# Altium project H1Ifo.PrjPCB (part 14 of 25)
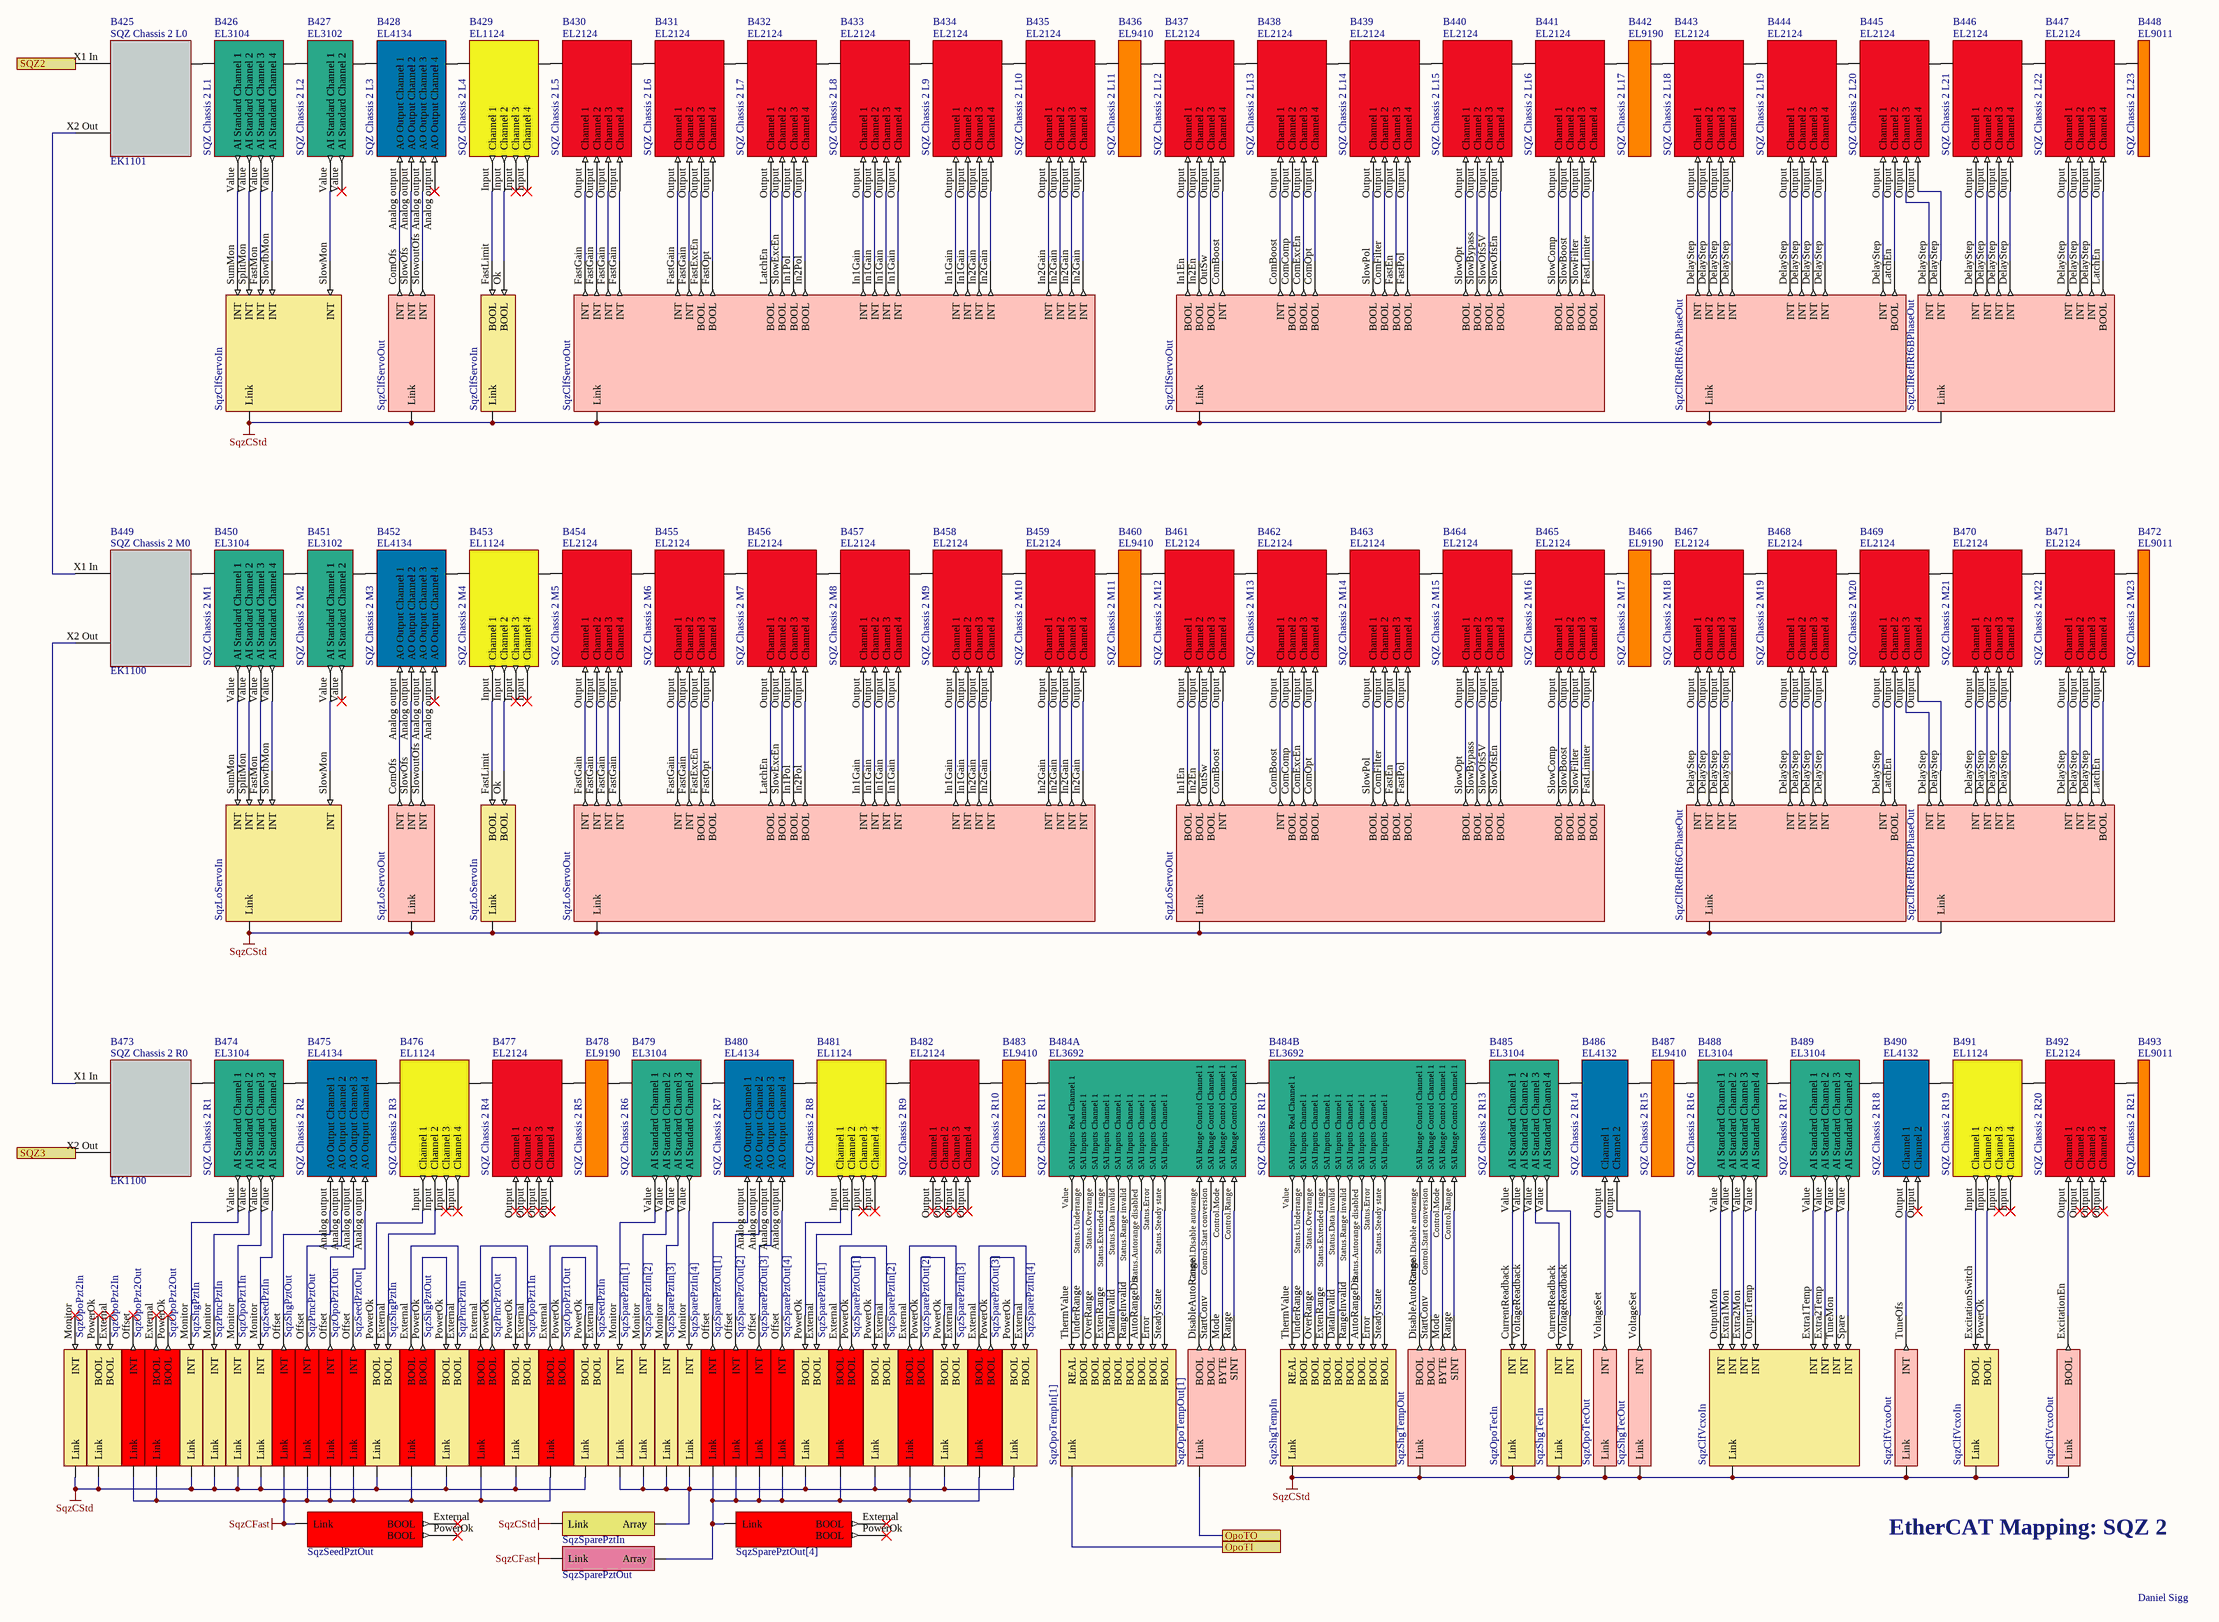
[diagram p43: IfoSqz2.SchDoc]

## Sheet IfoSqz2.SchDoc: D1800185 (continued)

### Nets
SqzCFast: V309.0(Link) V309.1(Link) V310.0(Link) V310.1(Link) V311.0(Link) V311.1(Link) V312.0(Link) V312.1(Link) V458.?1(Link) V668.0(Link) V668.1(Link)
SqzCStd: V176.1(Link) V177.1(Link) V289.0(Link) V289.1(Link) V290.0(Link) V290.1(Link) V290.2(Link) V291.0(Link) V291.1(Link) V292.0(Link) V292.1(Link) V292.2(Link) V297.1(Link) V298.1(Link) V303.0(Link) V303.1(Link) V304.0(Link) V304.1(Link) V305.0(Link) V305.1(Link) V306.0(Link) V306.1(Link) V307.0(Link) V307.1(Link) V308.0(Link) V308.1(Link) V448.?1(Link) V449.?1(Link) V450.?1(Link) V452.?1(Link) V455.1(Link) V456.1(Link) V457.?1(Link) V655.0(Link) V655.1(Link)
NetB409_X2 Out: B425.X1_In(A) ; port SQZ2
NetB425_Ebus: B425.Ebus(B) B426.Ebus(A)
NetB425_X2 Out: B425.X2_Out(C) B449.X1_In(A)
NetB426_Ebus: B426.Ebus(B) B427.Ebus(A)
NetB426_Value: B426.Value(AI_Standard_Channel_1) V291.SumMon(INT)
NetB426_Value: B426.Value(AI_Standard_Channel_2) V291.SplitMon(INT)  [a separate net that carries the same name]
NetB426_Value: B426.Value(AI_Standard_Channel_3) V291.FastMon(INT)  [a separate net that carries the same name]
NetB426_Value: B426.Value(AI_Standard_Channel_4) V291.SlowfbMon(INT)  [a separate net that carries the same name]
NetB427_Ebus: B427.Ebus(B) B428.Ebus(A)
NetB427_Value: B427.Value(AI_Standard_Channel_1) V291.SlowMon(INT)
NetB428_Analog output: B428.Analog_output(AO_Output_Channel_1) V292.ComOfs(INT)
NetB428_Analog output: B428.Analog_output(AO_Output_Channel_2) V292.SlowOfs(INT)  [a separate net that carries the same name]
NetB428_Analog output: B428.Analog_output(AO_Output_Channel_3) V292.SlowoutOfs(INT)  [a separate net that carries the same name]
NetB428_Ebus: B428.Ebus(B) B429.Ebus(A)
NetB429_Ebus: B429.Ebus(B) B430.Ebus(A)
NetB429_Input: B429.Input(Channel_1) V291.FastLimit(BOOL)
NetB429_Input: B429.Input(Channel_2) V291.Ok(BOOL)  [a separate net that carries the same name]
NetB430_Ebus: B430.Ebus(B) B431.Ebus(A)
NetB430_Output: B430.Output(Channel_1) V292.FastGain(INT)
NetB430_Output: B430.Output(Channel_2) V292.FastGain(INT)  [a separate net that carries the same name]
NetB430_Output: B430.Output(Channel_3) V292.FastGain(INT)  [a separate net that carries the same name]
NetB430_Output: B430.Output(Channel_4) V292.FastGain(INT)  [a separate net that carries the same name]
NetB431_Ebus: B431.Ebus(B) B432.Ebus(A)
NetB431_Output: B431.Output(Channel_1) V292.FastGain(INT)
NetB431_Output: B431.Output(Channel_2) V292.FastGain(INT)  [a separate net that carries the same name]
NetB431_Output: B431.Output(Channel_3) V292.FastExcEn(BOOL)  [a separate net that carries the same name]
NetB431_Output: B431.Output(Channel_4) V292.FastOpt(BOOL)  [a separate net that carries the same name]
NetB432_Ebus: B432.Ebus(B) B433.Ebus(A)
NetB432_Output: B432.Output(Channel_1) V292.LatchEn(BOOL)
NetB432_Output: B432.Output(Channel_2) V292.SlowExcEn(BOOL)  [a separate net that carries the same name]
NetB432_Output: B432.Output(Channel_3) V292.In1Pol(BOOL)  [a separate net that carries the same name]
NetB432_Output: B432.Output(Channel_4) V292.In2Pol(BOOL)  [a separate net that carries the same name]
NetB433_Ebus: B433.Ebus(B) B434.Ebus(A)
NetB433_Output: B433.Output(Channel_1) V292.In1Gain(INT)
NetB433_Output: B433.Output(Channel_2) V292.In1Gain(INT)  [a separate net that carries the same name]
NetB433_Output: B433.Output(Channel_3) V292.In1Gain(INT)  [a separate net that carries the same name]
NetB433_Output: B433.Output(Channel_4) V292.In1Gain(INT)  [a separate net that carries the same name]
NetB434_Ebus: B434.Ebus(B) B435.Ebus(A)
NetB434_Output: B434.Output(Channel_1) V292.In1Gain(INT)
NetB434_Output: B434.Output(Channel_2) V292.In1Gain(INT)  [a separate net that carries the same name]
NetB434_Output: B434.Output(Channel_3) V292.In2Gain(INT)  [a separate net that carries the same name]
NetB434_Output: B434.Output(Channel_4) V292.In2Gain(INT)  [a separate net that carries the same name]
NetB435_Ebus: B435.Ebus(B) B436.Ebus(A)
NetB435_Output: B435.Output(Channel_1) V292.In2Gain(INT)
NetB435_Output: B435.Output(Channel_2) V292.In2Gain(INT)  [a separate net that carries the same name]
NetB435_Output: B435.Output(Channel_3) V292.In2Gain(INT)  [a separate net that carries the same name]
NetB435_Output: B435.Output(Channel_4) V292.In2Gain(INT)  [a separate net that carries the same name]
NetB436_Ebus: B436.Ebus(B) B437.Ebus(A)
NetB437_Ebus: B437.Ebus(B) B438.Ebus(A)
NetB437_Output: B437.Output(Channel_1) V292.In1En(BOOL)
NetB437_Output: B437.Output(Channel_2) V292.In2En(BOOL)  [a separate net that carries the same name]
NetB437_Output: B437.Output(Channel_3) V292.OutSw(BOOL)  [a separate net that carries the same name]
NetB437_Output: B437.Output(Channel_4) V292.ComBoost(INT)  [a separate net that carries the same name]
NetB438_Ebus: B438.Ebus(B) B439.Ebus(A)
NetB438_Output: B438.Output(Channel_1) V292.ComBoost(INT)
NetB438_Output: B438.Output(Channel_2) V292.ComComp(BOOL)  [a separate net that carries the same name]
NetB438_Output: B438.Output(Channel_3) V292.ComExcEn(BOOL)  [a separate net that carries the same name]
NetB438_Output: B438.Output(Channel_4) V292.ComOpt(BOOL)  [a separate net that carries the same name]
NetB439_Ebus: B439.Ebus(B) B440.Ebus(A)
NetB439_Output: B439.Output(Channel_1) V292.SlowPol(BOOL)
NetB439_Output: B439.Output(Channel_2) V292.ComFilter(BOOL)  [a separate net that carries the same name]
NetB439_Output: B439.Output(Channel_3) V292.FastEn(BOOL)  [a separate net that carries the same name]
NetB439_Output: B439.Output(Channel_4) V292.FastPol(BOOL)  [a separate net that carries the same name]
NetB440_Ebus: B440.Ebus(B) B441.Ebus(A)
NetB440_Output: B440.Output(Channel_1) V292.SlowOpt(BOOL)
NetB440_Output: B440.Output(Channel_2) V292.SlowBypass(BOOL)  [a separate net that carries the same name]
NetB440_Output: B440.Output(Channel_3) V292.SlowOfs5V(BOOL)  [a separate net that carries the same name]
NetB440_Output: B440.Output(Channel_4) V292.SlowOfsEn(BOOL)  [a separate net that carries the same name]
NetB441_Ebus: B441.Ebus(B) B442.Ebus(A)
NetB441_Output: B441.Output(Channel_1) V292.SlowComp(BOOL)
NetB441_Output: B441.Output(Channel_2) V292.SlowBoost(BOOL)  [a separate net that carries the same name]
NetB441_Output: B441.Output(Channel_3) V292.SlowFilter(BOOL)  [a separate net that carries the same name]
NetB441_Output: B441.Output(Channel_4) V292.FastLimiter(BOOL)  [a separate net that carries the same name]
NetB442_Ebus: B442.Ebus(B) B443.Ebus(A)
NetB443_Ebus: B443.Ebus(B) B444.Ebus(A)
NetB443_Output: B443.Output(Channel_1) V448.DelayStep(INT)
NetB443_Output: B443.Output(Channel_2) V448.DelayStep(INT)  [a separate net that carries the same name]
NetB443_Output: B443.Output(Channel_3) V448.DelayStep(INT)  [a separate net that carries the same name]
NetB443_Output: B443.Output(Channel_4) V448.DelayStep(INT)  [a separate net that carries the same name]
NetB444_Ebus: B444.Ebus(B) B445.Ebus(A)
NetB444_Output: B444.Output(Channel_1) V448.DelayStep(INT)
NetB444_Output: B444.Output(Channel_2) V448.DelayStep(INT)  [a separate net that carries the same name]
NetB444_Output: B444.Output(Channel_3) V448.DelayStep(INT)  [a separate net that carries the same name]
NetB444_Output: B444.Output(Channel_4) V448.DelayStep(INT)  [a separate net that carries the same name]
NetB445_Ebus: B445.Ebus(B) B446.Ebus(A)
NetB445_Output: B445.Output(Channel_1) V448.DelayStep(INT)
NetB445_Output: B445.Output(Channel_2) V448.LatchEn(BOOL)  [a separate net that carries the same name]
NetB445_Output: B445.Output(Channel_3) V449.DelayStep(INT)  [a separate net that carries the same name]
NetB445_Output: B445.Output(Channel_4) V449.DelayStep(INT)  [a separate net that carries the same name]
NetB446_Ebus: B446.Ebus(B) B447.Ebus(A)
NetB446_Output: B446.Output(Channel_1) V449.DelayStep(INT)
NetB446_Output: B446.Output(Channel_2) V449.DelayStep(INT)  [a separate net that carries the same name]
NetB446_Output: B446.Output(Channel_3) V449.DelayStep(INT)  [a separate net that carries the same name]
NetB446_Output: B446.Output(Channel_4) V449.DelayStep(INT)  [a separate net that carries the same name]
NetB447_Ebus: B447.Ebus(B) B448.Ebus(A)
NetB447_Output: B447.Output(Channel_1) V449.DelayStep(INT)
NetB447_Output: B447.Output(Channel_2) V449.DelayStep(INT)  [a separate net that carries the same name]
NetB447_Output: B447.Output(Channel_3) V449.DelayStep(INT)  [a separate net that carries the same name]
NetB447_Output: B447.Output(Channel_4) V449.LatchEn(BOOL)  [a separate net that carries the same name]
NetB449_Ebus: B449.Ebus(B) B450.Ebus(A)
NetB449_X2 Out: B449.X2_Out(C) B473.X1_In(A)
NetB450_Ebus: B450.Ebus(B) B451.Ebus(A)
NetB450_Value: B450.Value(AI_Standard_Channel_1) V289.SumMon(INT)
NetB450_Value: B450.Value(AI_Standard_Channel_2) V289.SplitMon(INT)  [a separate net that carries the same name]
NetB450_Value: B450.Value(AI_Standard_Channel_3) V289.FastMon(INT)  [a separate net that carries the same name]
NetB450_Value: B450.Value(AI_Standard_Channel_4) V289.SlowfbMon(INT)  [a separate net that carries the same name]
NetB451_Ebus: B451.Ebus(B) B452.Ebus(A)
NetB451_Value: B451.Value(AI_Standard_Channel_1) V289.SlowMon(INT)
NetB452_Analog output: B452.Analog_output(AO_Output_Channel_1) V290.ComOfs(INT)
NetB452_Analog output: B452.Analog_output(AO_Output_Channel_2) V290.SlowOfs(INT)  [a separate net that carries the same name]
NetB452_Analog output: B452.Analog_output(AO_Output_Channel_3) V290.SlowoutOfs(INT)  [a separate net that carries the same name]
NetB452_Ebus: B452.Ebus(B) B453.Ebus(A)
NetB453_Ebus: B453.Ebus(B) B454.Ebus(A)
NetB453_Input: B453.Input(Channel_1) V289.FastLimit(BOOL)
NetB453_Input: B453.Input(Channel_2) V289.Ok(BOOL)  [a separate net that carries the same name]
NetB454_Ebus: B454.Ebus(B) B455.Ebus(A)
NetB454_Output: B454.Output(Channel_1) V290.FastGain(INT)
NetB454_Output: B454.Output(Channel_2) V290.FastGain(INT)  [a separate net that carries the same name]
NetB454_Output: B454.Output(Channel_3) V290.FastGain(INT)  [a separate net that carries the same name]
NetB454_Output: B454.Output(Channel_4) V290.FastGain(INT)  [a separate net that carries the same name]
NetB455_Ebus: B455.Ebus(B) B456.Ebus(A)
NetB455_Output: B455.Output(Channel_1) V290.FastGain(INT)
NetB455_Output: B455.Output(Channel_2) V290.FastGain(INT)  [a separate net that carries the same name]
NetB455_Output: B455.Output(Channel_3) V290.FastExcEn(BOOL)  [a separate net that carries the same name]
NetB455_Output: B455.Output(Channel_4) V290.FastOpt(BOOL)  [a separate net that carries the same name]
NetB456_Ebus: B456.Ebus(B) B457.Ebus(A)
NetB456_Output: B456.Output(Channel_1) V290.LatchEn(BOOL)
NetB456_Output: B456.Output(Channel_2) V290.SlowExcEn(BOOL)  [a separate net that carries the same name]
NetB456_Output: B456.Output(Channel_3) V290.In1Pol(BOOL)  [a separate net that carries the same name]
NetB456_Output: B456.Output(Channel_4) V290.In2Pol(BOOL)  [a separate net that carries the same name]
NetB457_Ebus: B457.Ebus(B) B458.Ebus(A)
NetB457_Output: B457.Output(Channel_1) V290.In1Gain(INT)
NetB457_Output: B457.Output(Channel_2) V290.In1Gain(INT)  [a separate net that carries the same name]
NetB457_Output: B457.Output(Channel_3) V290.In1Gain(INT)  [a separate net that carries the same name]
NetB457_Output: B457.Output(Channel_4) V290.In1Gain(INT)  [a separate net that carries the same name]
NetB458_Ebus: B458.Ebus(B) B459.Ebus(A)
NetB458_Output: B458.Output(Channel_1) V290.In1Gain(INT)
NetB458_Output: B458.Output(Channel_2) V290.In1Gain(INT)  [a separate net that carries the same name]
NetB458_Output: B458.Output(Channel_3) V290.In2Gain(INT)  [a separate net that carries the same name]
NetB458_Output: B458.Output(Channel_4) V290.In2Gain(INT)  [a separate net that carries the same name]
NetB459_Ebus: B459.Ebus(B) B460.Ebus(A)
NetB459_Output: B459.Output(Channel_1) V290.In2Gain(INT)
NetB459_Output: B459.Output(Channel_2) V290.In2Gain(INT)  [a separate net that carries the same name]
NetB459_Output: B459.Output(Channel_3) V290.In2Gain(INT)  [a separate net that carries the same name]
NetB459_Output: B459.Output(Channel_4) V290.In2Gain(INT)  [a separate net that carries the same name]
NetB460_Ebus: B460.Ebus(B) B461.Ebus(A)
NetB461_Ebus: B461.Ebus(B) B462.Ebus(A)
NetB461_Output: B461.Output(Channel_1) V290.In1En(BOOL)
NetB461_Output: B461.Output(Channel_2) V290.In2En(BOOL)  [a separate net that carries the same name]
NetB461_Output: B461.Output(Channel_3) V290.OutSw(BOOL)  [a separate net that carries the same name]
NetB461_Output: B461.Output(Channel_4) V290.ComBoost(INT)  [a separate net that carries the same name]
NetB462_Ebus: B462.Ebus(B) B463.Ebus(A)
NetB462_Output: B462.Output(Channel_1) V290.ComBoost(INT)
NetB462_Output: B462.Output(Channel_2) V290.ComComp(BOOL)  [a separate net that carries the same name]
NetB462_Output: B462.Output(Channel_3) V290.ComExcEn(BOOL)  [a separate net that carries the same name]
NetB462_Output: B462.Output(Channel_4) V290.ComOpt(BOOL)  [a separate net that carries the same name]
NetB463_Ebus: B463.Ebus(B) B464.Ebus(A)
NetB463_Output: B463.Output(Channel_1) V290.SlowPol(BOOL)
NetB463_Output: B463.Output(Channel_2) V290.ComFilter(BOOL)  [a separate net that carries the same name]
NetB463_Output: B463.Output(Channel_3) V290.FastEn(BOOL)  [a separate net that carries the same name]
NetB463_Output: B463.Output(Channel_4) V290.FastPol(BOOL)  [a separate net that carries the same name]
NetB464_Ebus: B464.Ebus(B) B465.Ebus(A)
NetB464_Output: B464.Output(Channel_1) V290.SlowOpt(BOOL)
NetB464_Output: B464.Output(Channel_2) V290.SlowBypass(BOOL)  [a separate net that carries the same name]
NetB464_Output: B464.Output(Channel_3) V290.SlowOfs5V(BOOL)  [a separate net that carries the same name]
NetB464_Output: B464.Output(Channel_4) V290.SlowOfsEn(BOOL)  [a separate net that carries the same name]
NetB465_Ebus: B465.Ebus(B) B466.Ebus(A)
NetB465_Output: B465.Output(Channel_1) V290.SlowComp(BOOL)
NetB465_Output: B465.Output(Channel_2) V290.SlowBoost(BOOL)  [a separate net that carries the same name]
NetB465_Output: B465.Output(Channel_3) V290.SlowFilter(BOOL)  [a separate net that carries the same name]
NetB465_Output: B465.Output(Channel_4) V290.FastLimiter(BOOL)  [a separate net that carries the same name]
NetB466_Ebus: B466.Ebus(B) B467.Ebus(A)
NetB467_Ebus: B467.Ebus(B) B468.Ebus(A)
NetB467_Output: B467.Output(Channel_1) V450.DelayStep(INT)
NetB467_Output: B467.Output(Channel_2) V450.DelayStep(INT)  [a separate net that carries the same name]
NetB467_Output: B467.Output(Channel_3) V450.DelayStep(INT)  [a separate net that carries the same name]
NetB467_Output: B467.Output(Channel_4) V450.DelayStep(INT)  [a separate net that carries the same name]
NetB468_Ebus: B468.Ebus(B) B469.Ebus(A)
NetB468_Output: B468.Output(Channel_1) V450.DelayStep(INT)
NetB468_Output: B468.Output(Channel_2) V450.DelayStep(INT)  [a separate net that carries the same name]
NetB468_Output: B468.Output(Channel_3) V450.DelayStep(INT)  [a separate net that carries the same name]
NetB468_Output: B468.Output(Channel_4) V450.DelayStep(INT)  [a separate net that carries the same name]
NetB469_Ebus: B469.Ebus(B) B470.Ebus(A)
NetB469_Output: B469.Output(Channel_1) V450.DelayStep(INT)
NetB469_Output: B469.Output(Channel_2) V450.LatchEn(BOOL)  [a separate net that carries the same name]
NetB469_Output: B469.Output(Channel_3) V452.DelayStep(INT)  [a separate net that carries the same name]
NetB469_Output: B469.Output(Channel_4) V452.DelayStep(INT)  [a separate net that carries the same name]
NetB470_Ebus: B470.Ebus(B) B471.Ebus(A)
NetB470_Output: B470.Output(Channel_1) V452.DelayStep(INT)
NetB470_Output: B470.Output(Channel_2) V452.DelayStep(INT)  [a separate net that carries the same name]
NetB470_Output: B470.Output(Channel_3) V452.DelayStep(INT)  [a separate net that carries the same name]
NetB470_Output: B470.Output(Channel_4) V452.DelayStep(INT)  [a separate net that carries the same name]
NetB471_Ebus: B471.Ebus(B) B472.Ebus(A)
NetB471_Output: B471.Output(Channel_1) V452.DelayStep(INT)
NetB471_Output: B471.Output(Channel_2) V452.DelayStep(INT)  [a separate net that carries the same name]
NetB471_Output: B471.Output(Channel_3) V452.DelayStep(INT)  [a separate net that carries the same name]
NetB471_Output: B471.Output(Channel_4) V452.LatchEn(BOOL)  [a separate net that carries the same name]
NetB473_Ebus: B473.Ebus(B) B474.Ebus(A)
NetB473_X2 Out: B473.X2_Out(C) ; port SQZ3
NetB474_Ebus: B474.Ebus(B) B475.Ebus(A)
NetB474_Value: B474.Value(AI_Standard_Channel_1) V305.Monitor(INT)
NetB474_Value: B474.Value(AI_Standard_Channel_2) V306.Monitor(INT)  [a separate net that carries the same name]
NetB474_Value: B474.Value(AI_Standard_Channel_3) V307.Monitor(INT)  [a separate net that carries the same name]
NetB474_Value: B474.Value(AI_Standard_Channel_4) V308.Monitor(INT)  [a separate net that carries the same name]
NetB475_Analog output: B475.Analog_output(AO_Output_Channel_1) V309.Offset(INT)
NetB475_Analog output: B475.Analog_output(AO_Output_Channel_2) V310.Offset(INT)  [a separate net that carries the same name]
NetB475_Analog output: B475.Analog_output(AO_Output_Channel_3) V311.Offset(INT)  [a separate net that carries the same name]
NetB475_Analog output: B475.Analog_output(AO_Output_Channel_4) V312.Offset(INT)  [a separate net that carries the same name]
NetB475_Ebus: B475.Ebus(B) B476.Ebus(A)
NetB476_Ebus: B476.Ebus(B) B477.Ebus(A)
NetB476_Input: B476.Input(Channel_1) V305.PowerOk(BOOL)
NetB476_Input: B476.Input(Channel_2) V305.External(BOOL)  [a separate net that carries the same name]
NetB477_Ebus: B477.Ebus(B) B478.Ebus(A)
NetB478_Ebus: B478.Ebus(B) B479.Ebus(A)
NetB479_Ebus: B479.Ebus(B) B480.Ebus(A)
NetB479_Value: B479.Value(AI_Standard_Channel_1) V313.Monitor(INT)
NetB479_Value: B479.Value(AI_Standard_Channel_2) V314.Monitor(INT)  [a separate net that carries the same name]
NetB479_Value: B479.Value(AI_Standard_Channel_3) V315.Monitor(INT)  [a separate net that carries the same name]
NetB479_Value: B479.Value(AI_Standard_Channel_4) V316.Monitor(INT)  [a separate net that carries the same name]
NetB480_Analog output: B480.Analog_output(AO_Output_Channel_1) V317.Offset(INT)
NetB480_Analog output: B480.Analog_output(AO_Output_Channel_2) V318.Offset(INT)  [a separate net that carries the same name]
NetB480_Analog output: B480.Analog_output(AO_Output_Channel_3) V319.Offset(INT)  [a separate net that carries the same name]
NetB480_Analog output: B480.Analog_output(AO_Output_Channel_4) V320.Offset(INT)  [a separate net that carries the same name]
NetB480_Ebus: B480.Ebus(B) B481.Ebus(A)
NetB481_Ebus: B481.Ebus(B) B482.Ebus(A)
NetB481_Input: B481.Input(Channel_1) V313.PowerOk(BOOL)
NetB481_Input: B481.Input(Channel_2) V313.External(BOOL)  [a separate net that carries the same name]
NetB482_Ebus: B482.Ebus(B) B483.Ebus(A)
NetB483_Ebus: B483.Ebus(B) B484A.Ebus(A)
NetB484A_Control.Disable autorange: B484A.Control.Disable_autorange(SAI_Range_Control_Channel_1) V454.DisableAutoRange(BOOL)
NetB484A_Control.Mode: B484A.Control.Mode(SAI_Range_Control_Channel_1) V454.Mode(BYTE)
NetB484A_Control.Range: B484A.Control.Range(SAI_Range_Control_Channel_1) V454.Range(SINT)
NetB484A_Control.Start conversion: B484A.Control.Start_conversion(SAI_Range_Control_Channel_1) V454.StartConv(BOOL)
NetB484A_Ebus: B484A.Ebus(B) B484B.Ebus(A)
NetB484A_Status.Autorange disabled: B484A.Status.Autorange_disabled(SAI_Inputs_Channel_1) V453.AutoRangeDis(BOOL)
NetB484A_Status.Data invalid: B484A.Status.Data_invalid(SAI_Inputs_Channel_1) V453.DataInvalid(BOOL)
NetB484A_Status.Error: B484A.Status.Error(SAI_Inputs_Channel_1) V453.Error(BOOL)
NetB484A_Status.Extended range: B484A.Status.Extended_range(SAI_Inputs_Channel_1) V453.ExtenRange(BOOL)
NetB484A_Status.Overrange: B484A.Status.Overrange(SAI_Inputs_Channel_1) V453.OverRange(BOOL)
NetB484A_Status.Range invalid: B484A.Status.Range_invalid(SAI_Inputs_Channel_1) V453.RangeInvalid(BOOL)
NetB484A_Status.Steady state: B484A.Status.Steady_state(SAI_Inputs_Channel_1) V453.SteadyState(BOOL)
NetB484A_Status.Underrange: B484A.Status.Underrange(SAI_Inputs_Channel_1) V453.UnderRange(BOOL)
NetB484A_Value: B484A.Value(SAI_Inputs_Real_Channel_1) V453.ThermValue(REAL)
NetB484B_Control.Disable autorange: B484B.Control.Disable_autorange(SAI_Range_Control_Channel_1) V298.DisableAutoRange(BOOL)
NetB484B_Control.Mode: B484B.Control.Mode(SAI_Range_Control_Channel_1) V298.Mode(BYTE)
NetB484B_Control.Range: B484B.Control.Range(SAI_Range_Control_Channel_1) V298.Range(SINT)
NetB484B_Control.Start conversion: B484B.Control.Start_conversion(SAI_Range_Control_Channel_1) V298.StartConv(BOOL)
NetB484B_Ebus: B484B.Ebus(B) B485.Ebus(A)
NetB484B_Status.Autorange disabled: B484B.Status.Autorange_disabled(SAI_Inputs_Channel_1) V297.AutoRangeDis(BOOL)
NetB484B_Status.Data invalid: B484B.Status.Data_invalid(SAI_Inputs_Channel_1) V297.DataInvalid(BOOL)
NetB484B_Status.Error: B484B.Status.Error(SAI_Inputs_Channel_1) V297.Error(BOOL)
NetB484B_Status.Extended range: B484B.Status.Extended_range(SAI_Inputs_Channel_1) V297.ExtenRange(BOOL)
NetB484B_Status.Overrange: B484B.Status.Overrange(SAI_Inputs_Channel_1) V297.OverRange(BOOL)
NetB484B_Status.Range invalid: B484B.Status.Range_invalid(SAI_Inputs_Channel_1) V297.RangeInvalid(BOOL)
NetB484B_Status.Steady state: B484B.Status.Steady_state(SAI_Inputs_Channel_1) V297.SteadyState(BOOL)
NetB484B_Status.Underrange: B484B.Status.Underrange(SAI_Inputs_Channel_1) V297.UnderRange(BOOL)
NetB484B_Value: B484B.Value(SAI_Inputs_Real_Channel_1) V297.ThermValue(REAL)
NetB485_Ebus: B485.Ebus(B) B486.Ebus(A)
NetB485_Value: B485.Value(AI_Standard_Channel_1) V455.CurrentReadback(INT)
NetB485_Value: B485.Value(AI_Standard_Channel_2) V455.VoltageReadback(INT)  [a separate net that carries the same name]
NetB485_Value: B485.Value(AI_Standard_Channel_3) V176.CurrentReadback(INT)  [a separate net that carries the same name]
NetB485_Value: B485.Value(AI_Standard_Channel_4) V176.VoltageReadback(INT)  [a separate net that carries the same name]
NetB486_Ebus: B486.Ebus(B) B487.Ebus(A)
NetB486_Output: B486.Output(Channel_1) V456.VoltageSet(INT)
NetB486_Output: B486.Output(Channel_2) V177.VoltageSet(INT)  [a separate net that carries the same name]
NetB487_Ebus: B487.Ebus(B) B488.Ebus(A)
NetB488_Ebus: B488.Ebus(B) B489.Ebus(A)
NetB488_Value: B488.Value(AI_Standard_Channel_1) V303.OutputMon(INT)
NetB488_Value: B488.Value(AI_Standard_Channel_2) V303.Extra1Mon(INT)  [a separate net that carries the same name]
NetB488_Value: B488.Value(AI_Standard_Channel_3) V303.Extra2Mon(INT)  [a separate net that carries the same name]
NetB488_Value: B488.Value(AI_Standard_Channel_4) V303.OutputTemp(INT)  [a separate net that carries the same name]
NetB489_Ebus: B489.Ebus(B) B490.Ebus(A)
NetB489_Value: B489.Value(AI_Standard_Channel_1) V303.Extra1Temp(INT)
NetB489_Value: B489.Value(AI_Standard_Channel_2) V303.Extra2Temp(INT)  [a separate net that carries the same name]
NetB489_Value: B489.Value(AI_Standard_Channel_3) V303.TuneMon(INT)  [a separate net that carries the same name]
NetB489_Value: B489.Value(AI_Standard_Channel_4) V303.Spare(INT)  [a separate net that carries the same name]
NetB490_Ebus: B490.Ebus(B) B491.Ebus(A)
NetB490_Output: B490.Output(Channel_1) V304.TuneOfs(INT)
NetB491_Ebus: B491.Ebus(B) B492.Ebus(A)
NetB491_Input: B491.Input(Channel_1) V303.ExcitationSwitch(BOOL)
NetB491_Input: B491.Input(Channel_2) V303.PowerOk(BOOL)  [a separate net that carries the same name]
NetB492_Ebus: B492.Ebus(B) B493.Ebus(A)
NetB492_Output: B492.Output(Channel_1) V304.ExcitationEn(BOOL)
NetV306_External: V306.External(BOOL) V309.External(BOOL)
NetV306_PowerOk: V306.PowerOk(BOOL) V309.PowerOk(BOOL)
NetV307_External: V307.External(BOOL) V310.External(BOOL)
NetV307_PowerOk: V307.PowerOk(BOOL) V310.PowerOk(BOOL)
NetV308_External: V308.External(BOOL) V311.External(BOOL)
NetV308_PowerOk: V308.PowerOk(BOOL) V311.PowerOk(BOOL)
NetV313_0: V313.0(Link) V313.1(Link) V314.0(Link) V314.1(Link) V315.0(Link) V315.1(Link) V316.0(Link) V316.1(Link) V457.?2(Array)
NetV314_External: V314.External(BOOL) V317.External(BOOL)
NetV314_PowerOk: V314.PowerOk(BOOL) V317.PowerOk(BOOL)
NetV315_External: V315.External(BOOL) V318.External(BOOL)
NetV315_PowerOk: V315.PowerOk(BOOL) V318.PowerOk(BOOL)
NetV316_External: V316.External(BOOL) V319.External(BOOL)
NetV316_PowerOk: V316.PowerOk(BOOL) V319.PowerOk(BOOL)
NetV317_0: V317.0(Link) V317.1(Link) V318.0(Link) V318.1(Link) V319.0(Link) V319.1(Link) V320.0(Link) V320.1(Link) V458.?2(Array)
NetV453_1: V453.1(Link) ; port OpoTI
NetV454_1: V454.1(Link) ; port OpoTO

Not connected (* = marked no-connect by the designer): B477 Output(Channel_1)*; B482 Output(Channel_1)*; V312 External(BOOL)* PowerOk(BOOL)*; V320 External(BOOL)* PowerOk(BOOL)*; V655 External(BOOL)* Monitor(INT)* PowerOk(BOOL)*; V668 External(BOOL)* Offset(INT)* PowerOk(BOOL)*

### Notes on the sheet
- EtherCAT Mapping: SQZ 2
- Daniel Sigg

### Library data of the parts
B425 = CouplerEK1101: EtherCAT Coupler; Rail: Left; BoxNextB: YIBSWSMK; BoxNextC: KEKDWQNR; BoxPrev: CHFWIWBW; PortPrevFull: 1044/C; PortPrevShort: C 'X2 Out'; Fullname: TIID^Vertex Squeezer (EtherCAT)^SQZ Chassis 2 L0 (EK1101); BoxPorts: Junction; BoxAddr: 1058; Disabled: False
B426 = TerminalEL3104: EtherCAT Terminal EL3104 4-chn Analog Input; Rail: Left; BoxNextB: UVXPPQLE; BoxPrev: HHKDCWNA; PortPrevFull: 1058/B; PortPrevShort: B; Fullname: TIID^Vertex Squeezer (EtherCAT)^SQZ Chassis 2 L0 (EK1101)^SQZ Chassis 2 L1 (EL3104); BoxAddr: 1059; Disabled: False
B427 = TerminalEL3102: EtherCAT Terminal EL3102 2-chn Analog Input; Rail: Left; BoxNextB: JWITNSNP; BoxPrev: YIBSWSMK; PortPrevFull: 1059/B; PortPrevShort: B; Fullname: TIID^Vertex Squeezer (EtherCAT)^SQZ Chassis 2 L0 (EK1101)^SQZ Chassis 2 L2 (EL3102); BoxAddr: 1060; Disabled: False
B428 = TerminalEL4134: EtherCAT Terminal EL4134 4-chn Analog Ouput; Rail: Left; BoxNextB: QUXVFVWX; BoxPrev: UVXPPQLE; PortPrevFull: 1060/B; PortPrevShort: B; Fullname: TIID^Vertex Squeezer (EtherCAT)^SQZ Chassis 2 L0 (EK1101)^SQZ Chassis 2 L3 (EL4134); BoxAddr: 1061; Disabled: False
B429 = TerminalEL1124: EtherCAT Terminal EL1124 4-chn Digital Input; Rail: Left; BoxNextB: CXNHHEGO; BoxPrev: JWITNSNP; PortPrevFull: 1061/B; PortPrevShort: B; Fullname: TIID^Vertex Squeezer (EtherCAT)^SQZ Chassis 2 L0 (EK1101)^SQZ Chassis 2 L4 (EL1124); BoxAddr: 1062; Disabled: False
B430 = TerminalEL2124: EtherCAT Terminal EL2124 4-chn Digital Ouput; Rail: Left; BoxNextB: ODRFWHAE; BoxPrev: QUXVFVWX; PortPrevFull: 1062/B; PortPrevShort: B; Fullname: TIID^Vertex Squeezer (EtherCAT)^SQZ Chassis 2 L0 (EK1101)^SQZ Chassis 2 L5 (EL2124); BoxAddr: 1063; Disabled: False
B431 = TerminalEL2124: EtherCAT Terminal EL2124 4-chn Digital Ouput; Rail: Left; BoxNextB: BALQWBRD; BoxPrev: CXNHHEGO; PortPrevFull: 1063/B; PortPrevShort: B; Fullname: TIID^Vertex Squeezer (EtherCAT)^SQZ Chassis 2 L0 (EK1101)^SQZ Chassis 2 L6 (EL2124); BoxAddr: 1064; Disabled: False
B432 = TerminalEL2124: EtherCAT Terminal EL2124 4-chn Digital Ouput; Rail: Left; BoxNextB: CLSSQIIU; BoxPrev: ODRFWHAE; PortPrevFull: 1064/B; PortPrevShort: B; Fullname: TIID^Vertex Squeezer (EtherCAT)^SQZ Chassis 2 L0 (EK1101)^SQZ Chassis 2 L7 (EL2124); BoxAddr: 1065; Disabled: False
B433 = TerminalEL2124: EtherCAT Terminal EL2124 4-chn Digital Ouput; Rail: Left; BoxNextB: PISMOMLF; BoxPrev: BALQWBRD; PortPrevFull: 1065/B; PortPrevShort: B; Fullname: TIID^Vertex Squeezer (EtherCAT)^SQZ Chassis 2 L0 (EK1101)^SQZ Chassis 2 L8 (EL2124); BoxAddr: 1066; Disabled: False
B434 = TerminalEL2124: EtherCAT Terminal EL2124 4-chn Digital Ouput; Rail: Left; BoxNextB: PQBBWYHF; BoxPrev: CLSSQIIU; PortPrevFull: 1066/B; PortPrevShort: B; Fullname: TIID^Vertex Squeezer (EtherCAT)^SQZ Chassis 2 L0 (EK1101)^SQZ Chassis 2 L9 (EL2124); BoxAddr: 1067; Disabled: False
B435 = TerminalEL2124: EtherCAT Terminal EL2124 4-chn Digital Ouput; Rail: Left; BoxNextB: DALVONDC; BoxPrev: PISMOMLF; PortPrevFull: 1067/B; PortPrevShort: B; Fullname: TIID^Vertex Squeezer (EtherCAT)^SQZ Chassis 2 L0 (EK1101)^SQZ Chassis 2 L10 (EL2124); BoxAddr: 1068; Disabled: False
B436 = TerminalEL9410: EtherCAT Terminal EL9410 Power; Rail: Left; BoxNextB: TJHWLYKT; BoxPrev: PQBBWYHF; PortPrevFull: 1068/B; PortPrevShort: B; Fullname: TIID^Vertex Squeezer (EtherCAT)^SQZ Chassis 2 L0 (EK1101)^SQZ Chassis 2 L11 (EL9410); BoxAddr: 1069; Disabled: False
B437 = TerminalEL2124: EtherCAT Terminal EL2124 4-chn Digital Ouput; Rail: Left; BoxNextB: HBAQLHEX; BoxPrev: DALVONDC; PortPrevFull: 1069/B; PortPrevShort: B; Fullname: TIID^Vertex Squeezer (EtherCAT)^SQZ Chassis 2 L0 (EK1101)^SQZ Chassis 2 L12 (EL2124); BoxAddr: 1070; Disabled: False
B438 = TerminalEL2124: EtherCAT Terminal EL2124 4-chn Digital Ouput; Rail: Left; BoxNextB: XIETYKNQ; BoxPrev: TJHWLYKT; PortPrevFull: 1070/B; PortPrevShort: B; Fullname: TIID^Vertex Squeezer (EtherCAT)^SQZ Chassis 2 L0 (EK1101)^SQZ Chassis 2 L13 (EL2124); BoxAddr: 1071; Disabled: False
B439 = TerminalEL2124: EtherCAT Terminal EL2124 4-chn Digital Ouput; Rail: Left; BoxNextB: UCOKAFSQ; BoxPrev: HBAQLHEX; PortPrevFull: 1071/B; PortPrevShort: B; Fullname: TIID^Vertex Squeezer (EtherCAT)^SQZ Chassis 2 L0 (EK1101)^SQZ Chassis 2 L14 (EL2124); BoxAddr: 1072; Disabled: False
B440 = TerminalEL2124: EtherCAT Terminal EL2124 4-chn Digital Ouput; Rail: Left; BoxNextB: LSKLHBHT; BoxPrev: XIETYKNQ; PortPrevFull: 1072/B; PortPrevShort: B; Fullname: TIID^Vertex Squeezer (EtherCAT)^SQZ Chassis 2 L0 (EK1101)^SQZ Chassis 2 L15 (EL2124); BoxAddr: 1073; Disabled: False
B441 = TerminalEL2124: EtherCAT Terminal EL2124 4-chn Digital Ouput; Rail: Left; BoxNextB: DBWMLABY; BoxPrev: UCOKAFSQ; PortPrevFull: 1073/B; PortPrevShort: B; Fullname: TIID^Vertex Squeezer (EtherCAT)^SQZ Chassis 2 L0 (EK1101)^SQZ Chassis 2 L16 (EL2124); BoxAddr: 1074; Disabled: False
B442 = TerminalEL9190: EtherCAT Terminal EL9190 Supply; BoxType: TerminalPassive; Rail: Left; BoxNextB: NTSQXXFD; BoxPrev: LSKLHBHT; PortPrevShort: B; Fullname: TIID^Vertex Squeezer (EtherCAT)^SQZ Chassis 2 L0 (EK1101)^SQZ Chassis 2 L17 (EL9190); Disabled: False
B443 = TerminalEL2124: EtherCAT Terminal EL2124 4-chn Digital Ouput; Rail: Left; BoxNextB: GJOXGWKF; BoxPrev: DBWMLABY; PortPrevFull: 1074/B; PortPrevShort: B; Fullname: TIID^Vertex Squeezer (EtherCAT)^SQZ Chassis 2 L0 (EK1101)^SQZ Chassis 2 L18 (EL2124); BoxAddr: 1075; Disabled: False
B444 = TerminalEL2124: EtherCAT Terminal EL2124 4-chn Digital Ouput; Rail: Left; BoxNextB: GXYGRGQH; BoxPrev: NTSQXXFD; PortPrevFull: 1075/B; PortPrevShort: B; Fullname: TIID^Vertex Squeezer (EtherCAT)^SQZ Chassis 2 L0 (EK1101)^SQZ Chassis 2 L19 (EL2124); BoxAddr: 1076; Disabled: False
B445 = TerminalEL2124: EtherCAT Terminal EL2124 4-chn Digital Ouput; Rail: Left; BoxNextB: PAXBBNHX; BoxPrev: GJOXGWKF; PortPrevFull: 1076/B; PortPrevShort: B; Fullname: TIID^Vertex Squeezer (EtherCAT)^SQZ Chassis 2 L0 (EK1101)^SQZ Chassis 2 L20 (EL2124); BoxAddr: 1077; Disabled: False
B446 = TerminalEL2124: EtherCAT Terminal EL2124 4-chn Digital Ouput; Rail: Left; BoxNextB: ENOUQMFN; BoxPrev: GXYGRGQH; PortPrevFull: 1077/B; PortPrevShort: B; Fullname: TIID^Vertex Squeezer (EtherCAT)^SQZ Chassis 2 L0 (EK1101)^SQZ Chassis 2 L21 (EL2124); BoxAddr: 1078; Disabled: False
B447 = TerminalEL2124: EtherCAT Terminal EL2124 4-chn Digital Ouput; Rail: Left; BoxNextB: BJEAUFSH; BoxPrev: PAXBBNHX; PortPrevFull: 1078/B; PortPrevShort: B; Fullname: TIID^Vertex Squeezer (EtherCAT)^SQZ Chassis 2 L0 (EK1101)^SQZ Chassis 2 L22 (EL2124); BoxAddr: 1079; Disabled: False
B448 = TerminalEL9011: EtherCAT Terminal EL9011 End; BoxType: TerminalPassive; Rail: Left; BoxPrev: ENOUQMFN; PortPrevShort: B; Fullname: TIID^Vertex Squeezer (EtherCAT)^SQZ Chassis 2 L0 (EK1101)^SQZ Chassis 2 L23 (EL9011); Disabled: False
B449 = CouplerEK1100: EtherCAT Coupler; Rail: Middle; BoxNextB: NGTXGYJV; BoxNextC: TJPFHJJD; BoxPrev: HHKDCWNA; PortPrevFull: 1058/C; PortPrevShort: C 'X2 Out'; Fullname: TIID^Vertex Squeezer (EtherCAT)^SQZ Chassis 2 M0 (EK1100); BoxPorts: Junction; BoxAddr: 1080; Disabled: False
B450 = TerminalEL3104: EtherCAT Terminal EL3104 4-chn Analog Input; Rail: Middle; BoxNextB: QIWRLFCU; BoxPrev: KEKDWQNR; PortPrevFull: 1080/B; PortPrevShort: B; Fullname: TIID^Vertex Squeezer (EtherCAT)^SQZ Chassis 2 M0 (EK1100)^SQZ Chassis 2 M1 (EL3104); BoxAddr: 1081; Disabled: False
B451 = TerminalEL3102: EtherCAT Terminal EL3102 2-chn Analog Input; Rail: Middle; BoxNextB: PTWDXKQX; BoxPrev: NGTXGYJV; PortPrevFull: 1081/B; PortPrevShort: B; Fullname: TIID^Vertex Squeezer (EtherCAT)^SQZ Chassis 2 M0 (EK1100)^SQZ Chassis 2 M2 (EL3102); BoxAddr: 1082; Disabled: False
B452 = TerminalEL4134: EtherCAT Terminal EL4134 4-chn Analog Ouput; Rail: Middle; BoxNextB: UWLMAKLT; BoxPrev: QIWRLFCU; PortPrevFull: 1082/B; PortPrevShort: B; Fullname: TIID^Vertex Squeezer (EtherCAT)^SQZ Chassis 2 M0 (EK1100)^SQZ Chassis 2 M3 (EL4134); BoxAddr: 1083; Disabled: False
B453 = TerminalEL1124: EtherCAT Terminal EL1124 4-chn Digital Input; Rail: Middle; BoxNextB: IAIBJMHQ; BoxPrev: PTWDXKQX; PortPrevFull: 1083/B; PortPrevShort: B; Fullname: TIID^Vertex Squeezer (EtherCAT)^SQZ Chassis 2 M0 (EK1100)^SQZ Chassis 2 M4 (EL1124); BoxAddr: 1084; Disabled: False
B454 = TerminalEL2124: EtherCAT Terminal EL2124 4-chn Digital Ouput; Rail: Middle; BoxNextB: RGTDOXVF; BoxPrev: UWLMAKLT; PortPrevFull: 1084/B; PortPrevShort: B; Fullname: TIID^Vertex Squeezer (EtherCAT)^SQZ Chassis 2 M0 (EK1100)^SQZ Chassis 2 M5 (EL2124); BoxAddr: 1085; Disabled: False
B455 = TerminalEL2124: EtherCAT Terminal EL2124 4-chn Digital Ouput; Rail: Middle; BoxNextB: KVTYJLKM; BoxPrev: IAIBJMHQ; PortPrevFull: 1085/B; PortPrevShort: B; Fullname: TIID^Vertex Squeezer (EtherCAT)^SQZ Chassis 2 M0 (EK1100)^SQZ Chassis 2 M6 (EL2124); BoxAddr: 1086; Disabled: False
B456 = TerminalEL2124: EtherCAT Terminal EL2124 4-chn Digital Ouput; Rail: Middle; BoxNextB: TOBVLKUR; BoxPrev: RGTDOXVF; PortPrevFull: 1086/B; PortPrevShort: B; Fullname: TIID^Vertex Squeezer (EtherCAT)^SQZ Chassis 2 M0 (EK1100)^SQZ Chassis 2 M7 (EL2124); BoxAddr: 1087; Disabled: False
B457 = TerminalEL2124: EtherCAT Terminal EL2124 4-chn Digital Ouput; Rail: Middle; BoxNextB: JGGYFHSJ; BoxPrev: KVTYJLKM; PortPrevFull: 1087/B; PortPrevShort: B; Fullname: TIID^Vertex Squeezer (EtherCAT)^SQZ Chassis 2 M0 (EK1100)^SQZ Chassis 2 M8 (EL2124); BoxAddr: 1088; Disabled: False
B458 = TerminalEL2124: EtherCAT Terminal EL2124 4-chn Digital Ouput; Rail: Middle; BoxNextB: ACHJHIYD; BoxPrev: TOBVLKUR; PortPrevFull: 1088/B; PortPrevShort: B; Fullname: TIID^Vertex Squeezer (EtherCAT)^SQZ Chassis 2 M0 (EK1100)^SQZ Chassis 2 M9 (EL2124); BoxAddr: 1089; Disabled: False
B459 = TerminalEL2124: EtherCAT Terminal EL2124 4-chn Digital Ouput; Rail: Middle; BoxNextB: DFKXJRMU; BoxPrev: JGGYFHSJ; PortPrevFull: 1089/B; PortPrevShort: B; Fullname: TIID^Vertex Squeezer (EtherCAT)^SQZ Chassis 2 M0 (EK1100)^SQZ Chassis 2 M10 (EL2124); BoxAddr: 1090; Disabled: False
B460 = TerminalEL9410: EtherCAT Terminal EL9410 Power; Rail: Middle; BoxNextB: XAAOCURT; BoxPrev: ACHJHIYD; PortPrevFull: 1090/B; PortPrevShort: B; Fullname: TIID^Vertex Squeezer (EtherCAT)^SQZ Chassis 2 M0 (EK1100)^SQZ Chassis 2 M11 (EL9410); BoxAddr: 1091; Disabled: False
B461 = TerminalEL2124: EtherCAT Terminal EL2124 4-chn Digital Ouput; Rail: Middle; BoxNextB: GJLQDDFA; BoxPrev: DFKXJRMU; PortPrevFull: 1091/B; PortPrevShort: B; Fullname: TIID^Vertex Squeezer (EtherCAT)^SQZ Chassis 2 M0 (EK1100)^SQZ Chassis 2 M12 (EL2124); BoxAddr: 1092; Disabled: False
B462 = TerminalEL2124: EtherCAT Terminal EL2124 4-chn Digital Ouput; Rail: Middle; BoxNextB: DPYFHTYO; BoxPrev: XAAOCURT; PortPrevFull: 1092/B; PortPrevShort: B; Fullname: TIID^Vertex Squeezer (EtherCAT)^SQZ Chassis 2 M0 (EK1100)^SQZ Chassis 2 M13 (EL2124); BoxAddr: 1093; Disabled: False
B463 = TerminalEL2124: EtherCAT Terminal EL2124 4-chn Digital Ouput; Rail: Middle; BoxNextB: LICMDICU; BoxPrev: GJLQDDFA; PortPrevFull: 1093/B; PortPrevShort: B; Fullname: TIID^Vertex Squeezer (EtherCAT)^SQZ Chassis 2 M0 (EK1100)^SQZ Chassis 2 M14 (EL2124); BoxAddr: 1094; Disabled: False
B464 = TerminalEL2124: EtherCAT Terminal EL2124 4-chn Digital Ouput; Rail: Middle; BoxNextB: ISSVUHXL; BoxPrev: DPYFHTYO; PortPrevFull: 1094/B; PortPrevShort: B; Fullname: TIID^Vertex Squeezer (EtherCAT)^SQZ Chassis 2 M0 (EK1100)^SQZ Chassis 2 M15 (EL2124); BoxAddr: 1095; Disabled: False
B465 = TerminalEL2124: EtherCAT Terminal EL2124 4-chn Digital Ouput; Rail: Middle; BoxNextB: WFLRRKHR; BoxPrev: LICMDICU; PortPrevFull: 1095/B; PortPrevShort: B; Fullname: TIID^Vertex Squeezer (EtherCAT)^SQZ Chassis 2 M0 (EK1100)^SQZ Chassis 2 M16 (EL2124); BoxAddr: 1096; Disabled: False
B466 = TerminalEL9190: EtherCAT Terminal EL9190 Supply; BoxType: TerminalPassive; Rail: Middle; BoxNextB: TNGLSLSY; BoxPrev: ISSVUHXL; PortPrevShort: B; Fullname: TIID^Vertex Squeezer (EtherCAT)^SQZ Chassis 2 M0 (EK1100)^SQZ Chassis 2 M17 (EL9190); Disabled: False
B467 = TerminalEL2124: EtherCAT Terminal EL2124 4-chn Digital Ouput; Rail: Middle; BoxNextB: JXFYXXNH; BoxPrev: WFLRRKHR; PortPrevFull: 1096/B; PortPrevShort: B; Fullname: TIID^Vertex Squeezer (EtherCAT)^SQZ Chassis 2 M0 (EK1100)^SQZ Chassis 2 M18 (EL2124); BoxAddr: 1097; Disabled: False
B468 = TerminalEL2124: EtherCAT Terminal EL2124 4-chn Digital Ouput; Rail: Middle; BoxNextB: XXVGFHMW; BoxPrev: TNGLSLSY; PortPrevFull: 1097/B; PortPrevShort: B; Fullname: TIID^Vertex Squeezer (EtherCAT)^SQZ Chassis 2 M0 (EK1100)^SQZ Chassis 2 M19 (EL2124); BoxAddr: 1098; Disabled: False
B469 = TerminalEL2124: EtherCAT Terminal EL2124 4-chn Digital Ouput; Rail: Middle; BoxNextB: KVMPJFCX; BoxPrev: JXFYXXNH; PortPrevFull: 1098/B; PortPrevShort: B; Fullname: TIID^Vertex Squeezer (EtherCAT)^SQZ Chassis 2 M0 (EK1100)^SQZ Chassis 2 M20 (EL2124); BoxAddr: 1099; Disabled: False
B470 = TerminalEL2124: EtherCAT Terminal EL2124 4-chn Digital Ouput; Rail: Middle; BoxNextB: JYDPXMHH; BoxPrev: XXVGFHMW; PortPrevFull: 1099/B; PortPrevShort: B; Fullname: TIID^Vertex Squeezer (EtherCAT)^SQZ Chassis 2 M0 (EK1100)^SQZ Chassis 2 M21 (EL2124); BoxAddr: 1100; Disabled: False
B471 = TerminalEL2124: EtherCAT Terminal EL2124 4-chn Digital Ouput; Rail: Middle; BoxNextB: QVPHBMVM; BoxPrev: KVMPJFCX; PortPrevFull: 1100/B; PortPrevShort: B; Fullname: TIID^Vertex Squeezer (EtherCAT)^SQZ Chassis 2 M0 (EK1100)^SQZ Chassis 2 M22 (EL2124); BoxAddr: 1101; Disabled: False
B472 = TerminalEL9011: EtherCAT Terminal EL9011 End; BoxType: TerminalPassive; Rail: Middle; BoxPrev: JYDPXMHH; PortPrevShort: B; Fullname: TIID^Vertex Squeezer (EtherCAT)^SQZ Chassis 2 M0 (EK1100)^SQZ Chassis 2 M23 (EL9011); Disabled: False
B473 = CouplerEK1100: EtherCAT Coupler; Rail: Right; BoxNextB: GEMNQVIM; BoxNextC: FMRHTNIC; BoxPrev: KEKDWQNR; PortPrevFull: 1080/C; PortPrevShort: C 'X2 Out'; Fullname: TIID^Vertex Squeezer (EtherCAT)^SQZ Chassis 2 R0 (EK1100); BoxPorts: Junction; BoxAddr: 1102; Disabled: False
B474 = TerminalEL3104: EtherCAT Terminal EL3104 4-chn Analog Input; Rail: Right; BoxNextB: VJNKGKXY; BoxPrev: TJPFHJJD; PortPrevFull: 1102/B; PortPrevShort: B; Fullname: TIID^Vertex Squeezer (EtherCAT)^SQZ Chassis 2 R0 (EK1100)^SQZ Chassis 2 R1 (EL3104); BoxAddr: 1103; Disabled: False
B475 = TerminalEL4134: EtherCAT Terminal EL4134 4-chn Analog Ouput; Rail: Right; BoxNextB: QKBBMNAB; BoxPrev: GEMNQVIM; PortPrevFull: 1103/B; PortPrevShort: B; Fullname: TIID^Vertex Squeezer (EtherCAT)^SQZ Chassis 2 R0 (EK1100)^SQZ Chassis 2 R2 (EL4134); BoxAddr: 1104; Disabled: False
B476 = TerminalEL1124: EtherCAT Terminal EL1124 4-chn Digital Input; Rail: Right; BoxNextB: JHGKSVGY; BoxPrev: VJNKGKXY; PortPrevFull: 1104/B; PortPrevShort: B; Fullname: TIID^Vertex Squeezer (EtherCAT)^SQZ Chassis 2 R0 (EK1100)^SQZ Chassis 2 R3 (EL1124); BoxAddr: 1105; Disabled: False
B477 = TerminalEL2124: EtherCAT Terminal EL2124 4-chn Digital Ouput; Rail: Right; BoxNextB: BVMLBIFG; BoxPrev: QKBBMNAB; PortPrevFull: 1105/B; PortPrevShort: B; Fullname: TIID^Vertex Squeezer (EtherCAT)^SQZ Chassis 2 R0 (EK1100)^SQZ Chassis 2 R4 (EL2124); BoxAddr: 1106; Disabled: False
B478 = TerminalEL9190: EtherCAT Terminal EL9190 Supply; BoxType: TerminalPassive; Rail: Right; BoxNextB: VAGEOOSP; BoxPrev: JHGKSVGY; PortPrevShort: B; Fullname: TIID^Vertex Squeezer (EtherCAT)^SQZ Chassis 2 R0 (EK1100)^SQZ Chassis 2 R5 (EL9190); Disabled: False
B479 = TerminalEL3104: EtherCAT Terminal EL3104 4-chn Analog Input; Rail: Right; BoxNextB: XJBMEULT; BoxPrev: BVMLBIFG; PortPrevFull: 1106/B; PortPrevShort: B; Fullname: TIID^Vertex Squeezer (EtherCAT)^SQZ Chassis 2 R0 (EK1100)^SQZ Chassis 2 R6 (EL3104); BoxAddr: 1107; Disabled: False
B480 = TerminalEL4134: EtherCAT Terminal EL4134 4-chn Analog Ouput; Rail: Right; BoxNextB: RNBXOCBR; BoxPrev: VAGEOOSP; PortPrevFull: 1107/B; PortPrevShort: B; Fullname: TIID^Vertex Squeezer (EtherCAT)^SQZ Chassis 2 R0 (EK1100)^SQZ Chassis 2 R7 (EL4134); BoxAddr: 1108; Disabled: False
B481 = TerminalEL1124: EtherCAT Terminal EL1124 4-chn Digital Input; Rail: Right; BoxNextB: XWJYRKTE; BoxPrev: XJBMEULT; PortPrevFull: 1108/B; PortPrevShort: B; Fullname: TIID^Vertex Squeezer (EtherCAT)^SQZ Chassis 2 R0 (EK1100)^SQZ Chassis 2 R8 (EL1124); BoxAddr: 1109; Disabled: False
B482 = TerminalEL2124: EtherCAT Terminal EL2124 4-chn Digital Ouput; Rail: Right; BoxNextB: MLKQECOF; BoxPrev: RNBXOCBR; PortPrevFull: 1109/B; PortPrevShort: B; Fullname: TIID^Vertex Squeezer (EtherCAT)^SQZ Chassis 2 R0 (EK1100)^SQZ Chassis 2 R9 (EL2124); BoxAddr: 1110; Disabled: False
B483 = TerminalEL9410: EtherCAT Terminal EL9410 Power; Rail: Right; BoxNextB: EMMUDPGB; BoxPrev: XWJYRKTE; PortPrevFull: 1110/B; PortPrevShort: B; Fullname: TIID^Vertex Squeezer (EtherCAT)^SQZ Chassis 2 R0 (EK1100)^SQZ Chassis 2 R10 (EL9410); BoxAddr: 1111; Disabled: False
B484A = TerminalEL3692-1chn: EtherCAT Terminal EL3692 1-chn Resistance Measurement; Rail: Right; BoxNextB: DPIIJDKN; BoxPrev: MLKQECOF; PortPrevFull: 1111/B; PortPrevShort: B; Fullname: TIID^Vertex Squeezer (EtherCAT)^SQZ Chassis 2 R0 (EK1100)^SQZ Chassis 2 R11 (EL3692); BoxAddr: 1112; PDO Inputs: 0x1A00,0x1A02; PDO Outputs: 0x1600; Disabled: False
B484B = TerminalEL3692-1chn: EtherCAT Terminal EL3692 1-chn Resistance Measurement; Rail: Right; BoxNextB: LQSXCDOO; BoxPrev: EMMUDPGB; PortPrevFull: 1112/B; PortPrevShort: B; Fullname: TIID^Vertex Squeezer (EtherCAT)^SQZ Chassis 2 R0 (EK1100)^SQZ Chassis 2 R12 (EL3692); BoxAddr: 1113; PDO Inputs: 0x1A00,0x1A02; PDO Outputs: 0x1600; Disabled: False
B485 = TerminalEL3104: EtherCAT Terminal EL3104 4-chn Analog Input; Rail: Right; BoxNextB: WHFEQRCM; BoxPrev: DPIIJDKN; PortPrevFull: 1113/B; PortPrevShort: B; Fullname: TIID^Vertex Squeezer (EtherCAT)^SQZ Chassis 2 R0 (EK1100)^SQZ Chassis 2 R13 (EL3104); BoxAddr: 1114; Disabled: False
B486 = TerminalEL4132: EtherCAT Terminal EL4132 2-chn Analog Ouput; Rail: Right; BoxNextB: EVBMIOGD; BoxPrev: LQSXCDOO; PortPrevFull: 1114/B; PortPrevShort: B; Fullname: TIID^Vertex Squeezer (EtherCAT)^SQZ Chassis 2 R0 (EK1100)^SQZ Chassis 2 R14 (EL4132); BoxAddr: 1115; Disabled: False
B487 = TerminalEL9410: EtherCAT Terminal EL9410 Power; Rail: Right; BoxNextB: EXEKQRDE; BoxPrev: WHFEQRCM; PortPrevFull: 1115/B; PortPrevShort: B; Fullname: TIID^Vertex Squeezer (EtherCAT)^SQZ Chassis 2 R0 (EK1100)^SQZ Chassis 2 R15 (EL9410); BoxAddr: 1116; Disabled: False
B488 = TerminalEL3104: EtherCAT Terminal EL3104 4-chn Analog Input; Rail: Right; BoxNextB: ICJBPXWX; BoxPrev: EVBMIOGD; PortPrevFull: 1116/B; PortPrevShort: B; Fullname: TIID^Vertex Squeezer (EtherCAT)^SQZ Chassis 2 R0 (EK1100)^SQZ Chassis 2 R16 (EL3104); BoxAddr: 1117; Disabled: False
B489 = TerminalEL3104: EtherCAT Terminal EL3104 4-chn Analog Input; Rail: Right; BoxNextB: VOQDLPUE; BoxPrev: EXEKQRDE; PortPrevFull: 1117/B; PortPrevShort: B; Fullname: TIID^Vertex Squeezer (EtherCAT)^SQZ Chassis 2 R0 (EK1100)^SQZ Chassis 2 R17 (EL3104); BoxAddr: 1118; Disabled: False
B490 = TerminalEL4132: EtherCAT Terminal EL4132 2-chn Analog Ouput; Rail: Right; BoxNextB: BWPPJVHC; BoxPrev: ICJBPXWX; PortPrevFull: 1118/B; PortPrevShort: B; Fullname: TIID^Vertex Squeezer (EtherCAT)^SQZ Chassis 2 R0 (EK1100)^SQZ Chassis 2 R18 (EL4132); BoxAddr: 1119; Disabled: False
B491 = TerminalEL1124: EtherCAT Terminal EL1124 4-chn Digital Input; Rail: Right; BoxNextB: MNOTQTNH; BoxPrev: VOQDLPUE; PortPrevFull: 1119/B; PortPrevShort: B; Fullname: TIID^Vertex Squeezer (EtherCAT)^SQZ Chassis 2 R0 (EK1100)^SQZ Chassis 2 R19 (EL1124); BoxAddr: 1120; Disabled: False
B492 = TerminalEL2124: EtherCAT Terminal EL2124 4-chn Digital Ouput; Rail: Right; BoxNextB: HGDXCXDM; BoxPrev: BWPPJVHC; PortPrevFull: 1120/B; PortPrevShort: B; Fullname: TIID^Vertex Squeezer (EtherCAT)^SQZ Chassis 2 R0 (EK1100)^SQZ Chassis 2 R20 (EL2124); BoxAddr: 1121; Disabled: False
B493 = TerminalEL9011: EtherCAT Terminal EL9011 End; BoxType: TerminalPassive; Rail: Right; BoxPrev: MNOTQTNH; PortPrevShort: B; Fullname: TIID^Vertex Squeezer (EtherCAT)^SQZ Chassis 2 R0 (EK1100)^SQZ Chassis 2 R21 (EL9011); Disabled: False
V176 V455 = TECController_TECDriverInStruct: TECDriverInStruct; BoxType: Variable; Instance: H1SqzCorner Instance; PLC: H1SqzCorner; Task: SqzCStd
V177 V456 = TECController_TECDriverOutStruct: TECDriverOutStruct; BoxType: Variable; Instance: H1SqzCorner Instance; PLC: H1SqzCorner; Task: SqzCStd
V289 V291 = CommonMode_CommonModeInStructB: CommonModeInStruct; BoxType: Variable; Instance: H1SqzCorner Instance; PLC: H1SqzCorner; Task: SqzCStd
V290 V292 = CommonMode_CommonModeOutStructB: CommonModeOutStruct; BoxType: Variable; Instance: H1SqzCorner Instance; PLC: H1SqzCorner; Task: SqzCStd
V297 V453 = TECController_ThermistorInStruct: ThermistorInStruct; BoxType: Variable; Instance: H1SqzCorner Instance; PLC: H1SqzCorner; Task: SqzCStd
V298 V454 = TECController_ThermistorOutStruct: ThermistorOutStruct; BoxType: Variable; Instance: H1SqzCorner Instance; PLC: H1SqzCorner; Task: SqzCStd
V303 = Vcxo_VcxoInStruct: VcxoInStruct; BoxType: Variable; Instance: H1SqzCorner Instance; PLC: H1SqzCorner; Task: SqzCStd
V304 = Vcxo_VcxoOutStruct: VcxoOutStruct; BoxType: Variable; Instance: H1SqzCorner Instance; PLC: H1SqzCorner; Task: SqzCStd
V305-V308 V313-V316 V655 = PztDriver_PztDriverInStruct: PztDriverInStruct; BoxType: Variable; Instance: H1SqzCorner Instance; PLC: H1SqzCorner; Task: SqzCStd
V309-V312 V317-V320 V668 = PztDriver_PztDriverFastOutStruct: PztDriverOutStruct; BoxType: Variable; Instance: H1SqzCorner Instance; PLC: H1SqzCorner; Task: SqzCFast
V448 V450 = DelayLogic_DelayLogicOutStruct: DelayLogicOutStruct; BoxType: Variable; Instance: H1SqzCorner Instance; PLC: H1SqzCorner; Task: SqzCStd
V449 V452 = DelayLogic_DelayLogicOutStructB: DelayLogicOutStruct; BoxType: Variable; Instance: H1SqzCorner Instance; PLC: H1SqzCorner; Task: SqzCStd
V457 = ArrayAggregatorIn: Array [1..4] Of PztDriverInStruct; Instance: H1SqzCorner Instance; PLC: H1SqzCorner; Task: SqzCStd; Lower Bound: 1; Upper Bound: 4
V458 = ArrayAggregatorOut: Array [1..4] Of PztDriverOutStruct; Instance: H1SqzCorner Instance; PLC: H1SqzCorner; Task: SqzCFast; Lower Bound: 1; Upper Bound: 4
